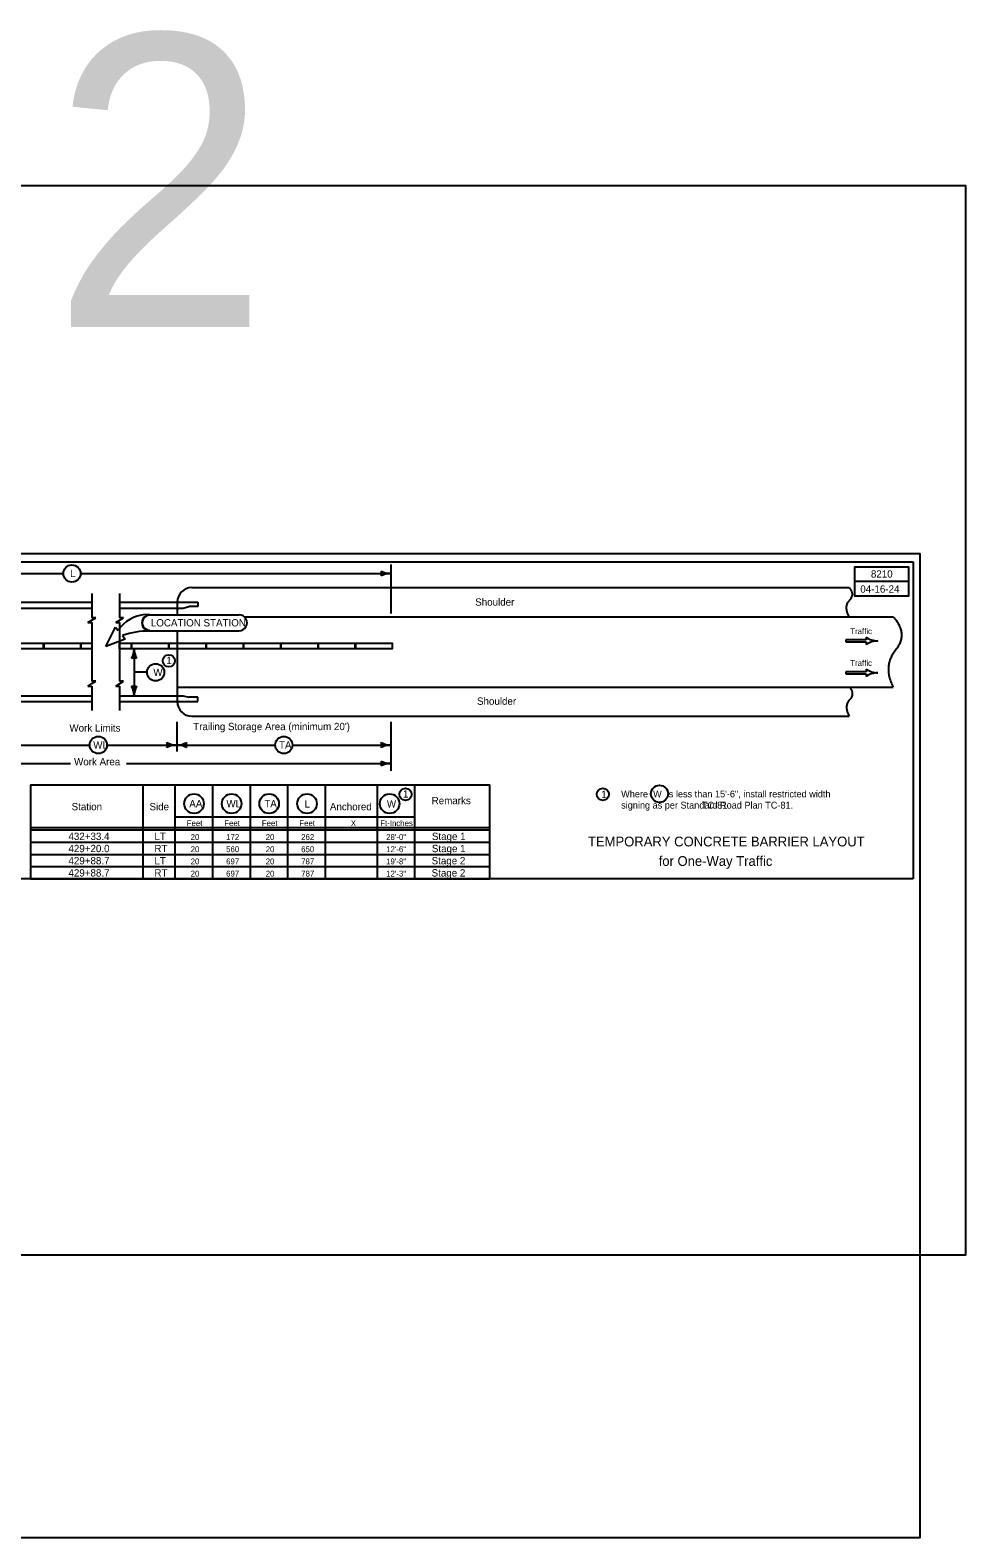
# Model space of a CAD drawing. Extents: x 10038 to 81668, y 7924 to 11018.
# Drawn here: x 15042 to 16962, y 7924 to 11018 of the extents above; entities that cross this region are included whole.
import ezdxf

# ---------------------------------------------------------------- set-up
doc = ezdxf.new("R2010")
doc.units = 0
for name, color, linetype in [('dsnCellElements', 7, 'Continuous'), ('DsnShtMinorGrid01', 7, 'Continuous'), ('Level 1', 7, 'Continuous'), ('Level 10', 7, 'Continuous'), ('Level 12', 7, 'Continuous'), ('Level 4', 7, 'Continuous'), ('Level 5', 7, 'Continuous'), ('Level 6', 7, 'Continuous'), ('Level 63', 7, 'Continuous'), ('SheetAddendum', 7, 'Continuous'), ('SheetBorder', 7, 'Continuous'), ('SheetText', 7, 'Continuous')]:
    doc.layers.add(name, color=color, linetype=linetype)

msp = doc.modelspace()

# ---------------------------------------------------------------- linework, layer by layer
at = {"layer": 'dsnCellElements'}
msp.add_lwpolyline([(13641.2, 8505), (16962.1, 8505), (16962.1, 10698.4), (13641.2, 10698.4)], close=True, dxfattribs=at)
at = {"layer": 'Level 1'}
for p, q in [((14232, 9903.1), (15110.6, 9903.1)), ((15145.9, 9903.1), (15782.6, 9903.1)), ((15782.6, 9921.7), (15782.6, 9820.9)), ((15374.3, 9874.1), (16722.7, 9874.1)), ((15022.9, 9844.1), (15168.9, 9844.1)), ((15168.9, 9862.1), (15168.9, 9812.3)), ((15226, 9862.1), (15226, 9812.3)), ((15226, 9844.1), (15344.3, 9844.1)), ((15344.3, 9844.1), (15386.3, 9844.1)), ((15344.3, 9844.1), (15344.3, 9818.1)), ((15386.3, 9844.1), (15386.3, 9835.1)), ((15022.9, 9832.1), (15168.9, 9832.1)), ((15168.9, 9807.2), (15176.9, 9812.3)), ((15176.9, 9812.3), (15168.9, 9812.3)), ((15218, 9802.2), (15234, 9812.3)), ((15226, 9832.1), (15344.3, 9832.1)), ((15234, 9812.3), (15226, 9812.3)), ((15278.4, 9818.7), (15287.9, 9819)), ((15287.9, 9819), (15287.9, 9817.2)), ((15287.9, 9818.1), (15471, 9818.1)), ((15344.3, 9832.1), (15356.3, 9832.1)), ((15356.3, 9832.1), (15368.3, 9835.1)), ((15386.3, 9835.1), (15368.3, 9835.1)), ((15481.8, 9814.1), (16813.1, 9814.1)), ((15160.9, 9802.2), (15168.9, 9807.2)), ((15160.9, 9802.2), (15168.9, 9802.2)), ((15168.9, 9802.2), (15168.9, 9742.1)), ((15197.4, 9753.1), (15217.5, 9793.1)), ((15217.5, 9793.1), (15223.2, 9786.1)), ((15218, 9802.2), (15226, 9802.2)), ((15226, 9802.2), (15226, 9742.1)), ((15287.9, 9786.5), (15287.9, 9784.7)), ((15287.9, 9785.6), (15471, 9785.6)), ((15344.3, 9785.6), (15344.3, 9640.1)), ((15237.6, 9768.1), (15197.4, 9753.1)), ((15231.7, 9775.5), (15237.6, 9768.1)), ((15255.6, 9748.4), (15255.6, 9652.1)), ((16757.4, 9767), (16716.2, 9767)), ((16716.2, 9767), (16716.2, 9762.5)), ((16716.2, 9762.5), (16757.4, 9762.5)), ((16757.4, 9772.2), (16757.4, 9767)), ((16757.4, 9762.5), (16757.4, 9757.2)), ((16781.3, 9764.7), (16781.3, 9764.7)), ((15168.9, 9742.1), (15168.9, 9682.1)), ((15226, 9742.1), (15226, 9682.1)), ((15282.2, 9700.3), (15255.6, 9700.3)), ((16757.4, 9701.5), (16716.2, 9701.5)), ((16716.2, 9701.5), (16716.2, 9697)), ((16716.2, 9697), (16757.4, 9697)), ((16757.4, 9706.8), (16757.4, 9701.5)), ((16757.4, 9697), (16757.4, 9691.8)), ((16781.3, 9699.3), (16781.3, 9699.3)), ((15160.9, 9672), (15168.9, 9677)), ((15160.9, 9672), (15168.9, 9672)), ((15168.9, 9677), (15176.9, 9682.1)), ((15176.9, 9682.1), (15168.9, 9682.1)), ((15168.9, 9672), (15168.9, 9622.1)), ((15218, 9672), (15234, 9682.1)), ((15218, 9672), (15226, 9672)), ((15234, 9682.1), (15226, 9682.1)), ((15226, 9672), (15226, 9622.1)), ((15344.3, 9670.1), (16813.1, 9670.1)), ((15022.9, 9652.1), (15168.9, 9652.1)), ((15022.9, 9640.1), (15168.9, 9640.1)), ((15226, 9652.1), (15344.3, 9652.1)), ((15226, 9640.1), (15344.3, 9640.1)), ((15344.3, 9652.1), (15356.3, 9652.1)), ((15344.3, 9640.1), (15386.3, 9640.1)), ((15356.3, 9652.1), (15368.3, 9649.1)), ((15386.3, 9649.1), (15368.3, 9649.1)), ((15386.3, 9640.1), (15386.3, 9649.1)), ((15343.1, 9598.9), (15343.1, 9537.6)), ((15374.3, 9610.1), (16722.7, 9610.1)), ((15782.6, 9598.9), (15782.6, 9498)), ((15021.7, 9551.1), (15164.9, 9551.1)), ((15199.9, 9551.1), (15343.1, 9551.1)), ((15212.6, 9551.1), (15343.1, 9551.1)), ((15343.1, 9551.1), (15545.2, 9551.1)), ((15580.5, 9551.1), (15782.6, 9551.1)), ((14534.2, 9513.2), (15125, 9513.2)), ((15240.3, 9513.2), (15782.6, 9513.2)), ((15241.6, 9513.2), (15343.1, 9513.2)), ((15274.2, 9276.7), (15274.2, 9469.7)), ((15340.2, 9276.7), (15340.2, 9469.7)), ((15417.2, 9276.7), (15417.2, 9469.7)), ((15494.2, 9276.7), (15494.2, 9469.7)), ((15571.2, 9276.7), (15571.2, 9469.7)), ((15043.2, 9381.7), (15985.7, 9381.7)), ((15043.2, 9376.7), (15985.7, 9376.7)), ((15340.2, 9403.9), (15831.7, 9403.9))]:
    msp.add_line(p, q, dxfattribs=at)
for points in [[(14994.4, 9760.4), (15069.4, 9760.4), (15069.4, 9748.4), (14994.4, 9748.4)], [(15070.9, 9760.4), (15145.9, 9760.4), (15145.9, 9748.4), (15070.9, 9748.4)], [(15251.3, 9760.4), (15326.3, 9760.4), (15326.3, 9748.4), (15251.3, 9748.4)], [(15327.8, 9760.4), (15402.8, 9760.4), (15402.8, 9748.4), (15327.8, 9748.4)], [(15404.3, 9760.4), (15479.3, 9760.4), (15479.3, 9748.4), (15404.3, 9748.4)], [(15480.8, 9760.4), (15555.8, 9760.4), (15555.8, 9748.4), (15480.8, 9748.4)], [(15557.3, 9760.4), (15632.3, 9760.4), (15632.3, 9748.4), (15557.3, 9748.4)], [(15633.8, 9760.4), (15708.8, 9760.4), (15708.8, 9748.4), (15633.8, 9748.4)], [(15710.3, 9760.4), (15785.3, 9760.4), (15785.3, 9748.4), (15710.3, 9748.4)]]:
    msp.add_lwpolyline(points, close=True, dxfattribs=at)
for points in [[(15168.9, 9748.4), (15147.4, 9748.4), (15147.4, 9760.4), (15168.9, 9760.4)], [(15168.9, 9760.4), (15168.9, 9748.4)], [(15226, 9748.4), (15226, 9760.4)], [(15226, 9760.4), (15249.8, 9760.4), (15249.8, 9748.4), (15226, 9748.4)]]:
    msp.add_lwpolyline(points, dxfattribs=at)
for centre, radius in [((15128.2, 9903.1), 17.6), ((15299.8, 9700.3), 17.6), ((15327, 9723.7), 12.5), ((15182.4, 9551.1), 17.6), ((15562.8, 9551.1), 17.6), ((16333.5, 9451), 17.6), ((15378.7, 9430.7), 20.1), ((15455.7, 9430.7), 20.1), ((15532.7, 9430.7), 20.1), ((15610.5, 9430.7), 20.1), ((15779.9, 9430.7), 20.1), ((15812.6, 9449.9), 12.5), ((16217.4, 9449.9), 12.5)]:
    msp.add_circle(centre, radius, dxfattribs=at)
for centre, radius, start, end in [((15746.9, 9903.1), 16.4, 342.2666, 17.7333), ((15782.6, 9945.6), 42.5, 241.9275, 270), ((15782.6, 9860.6), 42.5, 90, 118.0725), ((15374.3, 9844.1), 30, 90, 180), ((15213.1, 9748.4), 42.5, 331.9275, 0), ((15298.1, 9748.4), 42.5, 180, 208.0725), ((16783.3, 9813), 48.4, 237.618, 267.648), ((16783.3, 9716.4), 48.4, 92.352, 122.382), ((15255.6, 9712.8), 16.4, 72.2666, 107.7334), ((16783.3, 9747.6), 48.4, 237.618, 267.648), ((16783.3, 9651), 48.4, 92.352, 122.382), ((15255.6, 9687.8), 16.4, 252.2666, 287.7334), ((15213.1, 9652.1), 42.5, 0, 28.0725), ((15298.1, 9652.1), 42.5, 151.9275, 180), ((15374.3, 9640.1), 30, 180, 270), ((15307.4, 9551.1), 16.4, 342.2666, 17.7333), ((15343.1, 9593.6), 42.5, 241.9275, 270), ((15343.1, 9508.6), 42.5, 90, 118.0725), ((15343.1, 9593.6), 42.5, 270, 298.0725), ((15343.1, 9508.6), 42.5, 61.9275, 90), ((15378.7, 9551.1), 16.4, 162.2666, 197.7334), ((15746.9, 9551.1), 16.4, 342.2666, 17.7333), ((15782.6, 9593.6), 42.5, 241.9275, 270), ((15782.6, 9508.6), 42.5, 90, 118.0725), ((15746.9, 9513.2), 16.4, 342.2666, 17.7333), ((15782.6, 9555.7), 42.5, 241.9275, 270), ((15782.6, 9470.7), 42.5, 90, 118.0725)]:
    msp.add_arc(centre, radius, start, end, dxfattribs=at)
for centre, major_axis, start_param, end_param in [((15282.9, 9748.4), (-70.8, 0), 4.776871, 5.71778), ((15287.9, 9801.9), (-16.3, 0), 4.712389, 7.853982), ((15287.9, 9801.9), (15.4, 0), 1.570796, 4.712389), ((15471, 9801.9), (16.3, 0), 4.712389, 7.853982), ((15285, 9628.7), (-156.9, 0), 4.694293, 5.059134)]:
    msp.add_ellipse(centre, major_axis=major_axis, ratio=0.995025, start_param=start_param, end_param=end_param, dxfattribs=at)
for points in [[(16722.7, 9874.1), (16734.5, 9860), (16710.9, 9835), (16722.2, 9814.2)], [(16813.1, 9814.1), (16844.5, 9779.7), (16791.1, 9711.7), (16813.1, 9670.1)], [(16723.2, 9670.1), (16735, 9656), (16711.4, 9631), (16722.7, 9610.1)]]:
    msp.add_open_spline(points, degree=2, dxfattribs=at)
at = {"layer": 'Level 10'}
for p, q in [((13749.1, 9926.7), (16854.1, 9926.7)), ((16854.1, 9926.7), (16854.1, 9276.7))]:
    msp.add_line(p, q, dxfattribs=at)
at = {"layer": 'Level 4'}
msp.add_lwpolyline([(16844.1, 9916.7), (16844.1, 9856.7), (16734.1, 9856.7), (16734.1, 9916.7), (16844.1, 9916.7), (16844.1, 9886.7), (16734.1, 9886.7)], dxfattribs=at)
at = {"layer": 'Level 5'}
msp.add_line((16854.1, 9276.7), (13749.1, 9276.7), dxfattribs=at)
at = {"layer": 'Level 63'}
for p, q in [((15043.2, 9469.7), (15043.2, 9276.7)), ((15043.2, 9469.7), (15985.7, 9469.7)), ((15648.2, 9276.7), (15648.2, 9469.7)), ((15754.7, 9276.7), (15754.7, 9469.7)), ((15831.7, 9276.7), (15831.7, 9469.7)), ((15985.7, 9276.7), (15985.7, 9469.7))]:
    msp.add_line(p, q, dxfattribs=at)
at = {"layer": 'SheetAddendum'}
for p, q in [((15043.2, 9351.7), (15985.7, 9351.7)), ((15043.2, 9326.7), (15985.7, 9326.7)), ((15043.2, 9301.7), (15985.7, 9301.7)), ((15043.2, 9276.7), (15985.7, 9276.7))]:
    msp.add_line(p, q, dxfattribs=at)
at = {"layer": 'SheetBorder'}
msp.add_lwpolyline([(13732.5, 9944), (16867.5, 9944), (16867.5, 7924), (13732.5, 7924)], close=True, dxfattribs=at)

# ---------------------------------------------------------------- texts
at = {"layer": 'DsnShtMinorGrid01'}
for s, p in [('8210', (16767.3, 9894.7)), ('04-16-24', (16745.6, 9863.7))]:
    msp.add_text(s, height=15, dxfattribs=at).set_placement(p)
at = {"layer": 'Level 12'}
for s, height, p in [('L', 15, (15124.3, 9895.6)), ('Shoulder', 15, (15955.5, 9837)), ('LOCATION STATION', 15, (15290, 9794.4)), ('Traffic', 12, (16724.9, 9778.7)), ('1', 15, (15321.7, 9717.1)), ('Traffic', 12, (16724.9, 9713.3)), ('W', 15, (15295.2, 9692.8)), ('Shoulder', 15, (15959.2, 9633.6)), ('Work Limits', 15, (15123, 9578.6)), ("Trailing Storage Area (minimum 20')", 15, (15377, 9581.6)), ('WL', 15, (15171.9, 9543.6)), ('TA', 15, (15553, 9543.6)), ('Work Area', 15, (15132.5, 9509.3)), ('AA', 15, (15368.9, 9423.2)), ('WL', 15, (15445.1, 9423.2)), ('TA', 15, (15522.8, 9423.2)), ('L', 15, (15605.5, 9422.8)), ('W', 15, (15774.3, 9422.8)), ('1', 15, (15807.4, 9443.3)), ('Remarks', 15, (15866.2, 9429.6)), ('1', 15, (16214, 9442.4)), ('Where  W  is less than 15\'-6", install restricted width', 14, (16254.9, 9443.6)), ('Station', 15, (15127.5, 9417.2)), ('Side', 15, (15287.2, 9417.2)), ('Anchored', 15, (15657.4, 9417.2)), ('signing as per Standard Road Plan TC-81.', 14, (16254.9, 9420.6)), ('                                TC-81', 14, (16254.2, 9420.6)), ('Feet', 12, (15363.7, 9384.7)), ('Feet', 12, (15440.7, 9384.7)), ('Feet', 12, (15517.7, 9384.7)), ('Feet', 12, (15594.7, 9384.7)), ('X', 12, (15700.3, 9384.7)), ('Ft-Inches', 12, (15760.7, 9384.7)), ('432+33.4', 15, (15121, 9356.2)), ('429+20.0', 15, (15121, 9331.2)), ('LT', 15, (15297.4, 9356.2)), ('RT', 15, (15297.4, 9331.2)), ('20', 12, (15371.7, 9356.2)), ('172', 12, (15444.5, 9356.2)), ('20', 12, (15525.7, 9356.2)), ('262', 12, (15598.5, 9356.2)), ('28\'-0"', 12, (15772.8, 9356.2)), ('Stage 1', 15, (15866.6, 9356.2)), ('Stage 1', 15, (15866.6, 9331.2)), ('429+88.7', 15, (15121, 9306.2)), ('LT', 15, (15297.4, 9306.2)), ('20', 12, (15371.7, 9331.2)), ('20', 12, (15371.7, 9306.2)), ('560', 12, (15444.5, 9331.2)), ('697', 12, (15444.5, 9306.2)), ('20', 12, (15525.7, 9331.2)), ('20', 12, (15525.7, 9306.2)), ('650', 12, (15598.5, 9331.2)), ('787', 12, (15598.5, 9306.2)), ('12\'-6"', 12, (15772.8, 9331.2)), ('19\'-8"', 12, (15772.8, 9306.2)), ('Stage 2', 15, (15866.1, 9306.2)), ('429+88.7', 15, (15121, 9281.2)), ('RT', 15, (15297.4, 9281.2)), ('20', 12, (15371.7, 9281.2)), ('697', 12, (15444.5, 9281.2)), ('20', 12, (15525.7, 9281.2)), ('787', 12, (15598.5, 9281.2)), ('12\'-3"', 12, (15772.8, 9281.2)), ('Stage 2', 15, (15866.1, 9281.2))]:
    msp.add_text(s, height=height, dxfattribs=at).set_placement(p)
at = {"layer": 'Level 6'}
for s, p in [('TEMPORARY CONCRETE BARRIER LAYOUT', (16186.8, 9343)), ('for One-Way Traffic', (16331.9, 9303))]:
    msp.add_text(s, height=20, dxfattribs=at).set_placement(p)
at = {"layer": 'SheetText'}
msp.add_text('2', height=600, dxfattribs=at).set_placement((15085.9, 10409.2))

doc.saveas('drawing.dxf')
